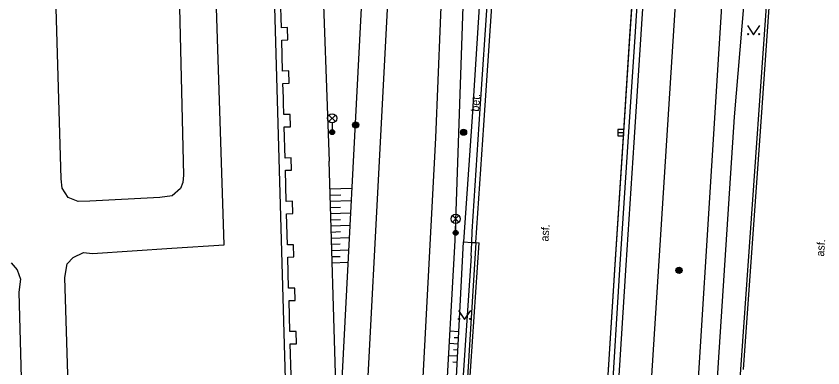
# Model space of a CAD drawing. Extents: x -599951 to -598963, y -1164095 to -1162939.
# Drawn here: x -599227.3 to -599161.8, y -1163894.3 to -1163865.7 of the extents above; entities that cross this region are included whole.
import ezdxf

# ---------------------------------------------------------------- set-up
doc = ezdxf.new("R2010")
doc.units = 0
for name, color, linetype in [('Level 1', 7, 'Continuous'), ('Level 10', 7, 'Continuous'), ('Level 11', 7, 'Continuous'), ('Level 13', 7, 'Continuous'), ('Level 14', 7, 'Continuous'), ('Level 15', 7, 'Continuous'), ('Level 25', 7, 'Continuous'), ('Level 27', 7, 'Continuous'), ('Level 33', 7, 'Continuous'), ('Level 36', 7, 'Continuous'), ('Level 40', 7, 'Continuous'), ('Level 54', 7, 'Continuous'), ('Level 9', 7, 'Continuous')]:
    doc.layers.add(name, color=color, linetype=linetype)

msp = doc.modelspace()

# ---------------------------------------------------------------- linework, layer by layer
at = {"layer": 'Level 1'}
msp.add_lwpolyline([(-599204.94, -1163894.86), (-599205.01, -1163892.33), (-599204.51, -1163892.32), (-599204.54, -1163891.32), (-599205.04, -1163891.33), (-599205.11, -1163888.8), (-599204.61, -1163888.79), (-599204.64, -1163887.79), (-599205.14, -1163887.8), (-599205.21, -1163885.27), (-599204.71, -1163885.26), (-599204.74, -1163884.26), (-599205.24, -1163884.27), (-599205.31, -1163881.74), (-599204.81, -1163881.73), (-599204.84, -1163880.73), (-599205.34, -1163880.74), (-599205.4, -1163878.21), (-599204.9, -1163878.2), (-599204.93, -1163877.2), (-599205.43, -1163877.22), (-599205.5, -1163874.69), (-599205, -1163874.67), (-599205.03, -1163873.67), (-599205.53, -1163873.69), (-599205.56, -1163872.71), (-599205.57, -1163872.31), (-599205.6, -1163871.16), (-599205.1, -1163871.14), (-599205.13, -1163870.14), (-599205.63, -1163870.16), (-599205.7, -1163867.63), (-599205.2, -1163867.61), (-599205.23, -1163866.61), (-599205.73, -1163866.63), (-599205.8, -1163864.1)], dxfattribs=at)
msp.add_lwpolyline([(-599204.94, -1163894.86), (-599205.01, -1163892.33), (-599204.51, -1163892.32), (-599204.54, -1163891.32), (-599205.04, -1163891.33), (-599205.11, -1163888.8), (-599204.61, -1163888.79), (-599204.64, -1163887.79), (-599205.14, -1163887.8), (-599205.21, -1163885.27), (-599204.71, -1163885.26), (-599204.74, -1163884.26), (-599205.24, -1163884.27), (-599205.31, -1163881.74), (-599204.81, -1163881.73), (-599204.84, -1163880.73), (-599205.34, -1163880.74), (-599205.4, -1163878.21), (-599204.9, -1163878.2), (-599204.93, -1163877.2), (-599205.43, -1163877.22), (-599205.5, -1163874.69), (-599205, -1163874.67), (-599205.03, -1163873.67), (-599205.53, -1163873.69), (-599205.56, -1163872.71), (-599205.57, -1163872.31), (-599205.6, -1163871.16), (-599205.1, -1163871.14), (-599205.13, -1163870.14), (-599205.63, -1163870.16), (-599205.7, -1163867.63), (-599205.2, -1163867.61), (-599205.23, -1163866.61), (-599205.73, -1163866.63), (-599205.8, -1163864.1)], dxfattribs=at)
at = {"layer": 'Level 10'}
for points in [[(-599162.85, -1163820.04), (-599165.66, -1163854.88), (-599168.46, -1163894.41), (-599171.02, -1163933.26), (-599173.23, -1163971.43)], [(-599162.85, -1163820.04), (-599165.66, -1163854.88), (-599168.46, -1163894.41), (-599171.02, -1163933.26), (-599173.23, -1163971.43)], [(-599189.93, -1163884.08), (-599190.81, -1163898.12), (-599192.15, -1163919.43), (-599193.42, -1163940)]]:
    msp.add_lwpolyline(points, dxfattribs=at)
at = {"layer": 'Level 11'}
for points in [[(-599189.93, -1163884.08), (-599189.3, -1163874.55), (-599188.64, -1163864.86), (-599187.94, -1163853.9), (-599187.18, -1163842.59), (-599186.48, -1163831.96), (-599185.77, -1163821.34), (-599185.17, -1163812.32)], [(-599189.93, -1163884.08), (-599189.3, -1163874.55), (-599188.64, -1163864.86), (-599187.94, -1163853.9), (-599187.18, -1163842.59), (-599186.48, -1163831.96), (-599185.77, -1163821.34), (-599185.17, -1163812.32)], [(-599172.9, -1163813.11), (-599173.38, -1163820.1), (-599174.07, -1163830.07), (-599174.74, -1163840.04), (-599175.4, -1163850), (-599175.95, -1163858.03), (-599176.47, -1163865.91), (-599177.1, -1163875.95), (-599177.75, -1163885.93), (-599178.52, -1163897.89), (-599179.3, -1163909.98), (-599179.92, -1163919.81), (-599180.51, -1163929.76), (-599181.12, -1163939.81), (-599181.72, -1163949.74), (-599182.32, -1163959.77), (-599182.91, -1163969.7), (-599183.49, -1163979.74), (-599184.17, -1163991.77), (-599185.17, -1164009.07), (-599185.26, -1164010.75)], [(-599172.9, -1163813.11), (-599173.38, -1163820.1), (-599174.07, -1163830.07), (-599174.74, -1163840.04), (-599175.4, -1163850), (-599175.95, -1163858.03), (-599176.47, -1163865.91), (-599177.1, -1163875.95), (-599177.75, -1163885.93), (-599178.52, -1163897.89), (-599179.3, -1163909.98), (-599179.92, -1163919.81), (-599180.51, -1163929.76), (-599181.12, -1163939.81), (-599181.72, -1163949.74), (-599182.32, -1163959.77), (-599182.91, -1163969.7), (-599183.49, -1163979.74), (-599184.17, -1163991.77), (-599185.17, -1164009.07), (-599185.26, -1164010.75)], [(-599197.62, -1163823.43), (-599198.25, -1163843.69), (-599199.2, -1163863.95), (-599200.91, -1163896.76), (-599202.16, -1163918.73), (-599203.28, -1163939.73), (-599203.53, -1163944.26), (-599203.97, -1163952.36)], [(-599197.62, -1163823.43), (-599198.25, -1163843.69), (-599199.2, -1163863.95), (-599200.91, -1163896.76), (-599202.16, -1163918.73), (-599203.28, -1163939.73), (-599203.53, -1163944.26), (-599203.97, -1163952.36)], [(-599203.73, -1163825.91), (-599201.86, -1163877.48)], [(-599180.56, -1163916.59), (-599180.15, -1163909.9), (-599179.38, -1163897.86), (-599178.63, -1163885.9), (-599177.98, -1163875.98), (-599177.45, -1163867.9), (-599176.79, -1163857.91), (-599176.26, -1163849.92), (-599175.61, -1163839.95), (-599175.02, -1163831.17)], [(-599165.76, -1163834.08), (-599167.29, -1163853.99), (-599168.96, -1163873.88)], [(-599165.44, -1163854.9), (-599166.83, -1163874.66), (-599168.22, -1163894.41)], [(-599189.35, -1163860.2), (-599189.55, -1163863.18), (-599190.25, -1163873.87), (-599190.93, -1163884.04)], [(-599191.62, -1163883.93), (-599190.97, -1163864.91)], [(-599168.96, -1163873.88), (-599170.26, -1163893.84), (-599171.48, -1163913.8)], [(-599195.85, -1163959.31), (-599194.73, -1163939.87), (-599193.59, -1163919.49), (-599192.41, -1163897.89), (-599191.62, -1163883.93)], [(-599190.93, -1163884.04), (-599190.27, -1163884.07)], [(-599190.27, -1163884.07), (-599189.93, -1163884.08)], [(-599190.62, -1163898.15), (-599189.67, -1163884.1)], [(-599189.93, -1163884.08), (-599189.67, -1163884.1)]]:
    msp.add_lwpolyline(points, dxfattribs=at)
at = {"layer": 'Level 13'}
for points in [[(-599178.43, -1164000.2), (-599167.24, -1163821.2)], [(-599191.12, -1163824.29), (-599193.21, -1163875.57)], [(-599196.66, -1163855.83), (-599199.93, -1163918.11)], [(-599173.6, -1163862.17), (-599182.35, -1163999.95)], [(-599193.21, -1163875.57), (-599199.31, -1163990.76)]]:
    msp.add_lwpolyline(points, dxfattribs=at)
at = {"layer": 'Level 14'}
msp.add_lwpolyline([(-599196.72, -1163973.49), (-599195.22, -1163960.9), (-599193.97, -1163939.87), (-599192.41, -1163912.27), (-599190.93, -1163884.04)], dxfattribs=at)
at = {"layer": 'Level 15'}
for points in [[(-599201.79, -1163879.73), (-599200.02, -1163879.67)], [(-599201.77, -1163880.23), (-599200.91, -1163880.2)], [(-599201.76, -1163880.73), (-599200.07, -1163880.68)], [(-599201.74, -1163881.23), (-599200.92, -1163881.2)], [(-599201.73, -1163881.73), (-599200.13, -1163881.68)], [(-599201.71, -1163882.23), (-599200.93, -1163882.2)], [(-599201.7, -1163882.73), (-599200.18, -1163882.68)], [(-599201.68, -1163883.23), (-599200.94, -1163883.2)], [(-599201.67, -1163883.73), (-599200.23, -1163883.68)], [(-599201.65, -1163884.23), (-599200.95, -1163884.2)], [(-599201.64, -1163884.73), (-599200.28, -1163884.69)], [(-599201.62, -1163885.23), (-599200.97, -1163885.21)], [(-599201.61, -1163885.73), (-599200.34, -1163885.69)], [(-599191.31, -1163891.34), (-599192.04, -1163891.3)], [(-599191.34, -1163891.84), (-599191.7, -1163891.82)], [(-599191.37, -1163892.34), (-599192.09, -1163892.3)], [(-599191.39, -1163892.83), (-599191.76, -1163892.82)], [(-599191.42, -1163893.33), (-599192.15, -1163893.3)], [(-599191.44, -1163893.83), (-599191.81, -1163893.81)]]:
    msp.add_lwpolyline(points, dxfattribs=at)
at = {"layer": 'Level 25'}
for centre, radius in [((-599199.7, -1163874.52), 0.25), ((-599199.7, -1163874.52), 0.2), ((-599199.7, -1163874.52), 0.15), ((-599199.7, -1163874.52), 0.1), ((-599199.7, -1163874.52), 0.05), ((-599190.94, -1163875.12), 0.25), ((-599190.94, -1163875.12), 0.2), ((-599190.94, -1163875.12), 0.15), ((-599190.94, -1163875.12), 0.1), ((-599190.94, -1163875.12), 0.05), ((-599173.44, -1163886.35), 0.25), ((-599173.44, -1163886.35), 0.2), ((-599173.44, -1163886.35), 0.15), ((-599173.44, -1163886.35), 0.1), ((-599173.44, -1163886.35), 0.05)]:
    msp.add_circle(centre, radius, dxfattribs=at)
at = {"layer": 'Level 27'}
msp.add_line((-599178.42, -1163875.15), (-599177.92, -1163875.15), dxfattribs=at)
msp.add_lwpolyline([(-599178.42, -1163875.4), (-599177.92, -1163875.4), (-599177.92, -1163874.9), (-599178.42, -1163874.9)], close=True, dxfattribs=at)
at = {"layer": 'Level 33'}
for p, q in [((-599201.875, -1163874.25), (-599201.345, -1163873.72)), ((-599201.875, -1163873.72), (-599201.345, -1163874.25)), ((-599201.61, -1163874.36), (-599201.61, -1163875.11)), ((-599191.845, -1163882.43), (-599191.315, -1163881.9)), ((-599191.845, -1163881.9), (-599191.315, -1163882.43)), ((-599191.58, -1163882.54), (-599191.58, -1163883.29))]:
    msp.add_line(p, q, dxfattribs=at)
for centre, radius in [((-599201.61, -1163873.985), 0.375), ((-599201.61, -1163875.11), 0.2), ((-599201.61, -1163875.11), 0.145), ((-599201.61, -1163875.11), 0.0876), ((-599191.58, -1163882.165), 0.375), ((-599191.58, -1163883.29), 0.2), ((-599191.58, -1163883.29), 0.145), ((-599191.58, -1163883.29), 0.0876)]:
    msp.add_circle(centre, radius, dxfattribs=at)
at = {"layer": 'Level 36'}
for points in [[(-599167.88, -1163866.45), (-599167.38, -1163867.2), (-599166.88, -1163866.45)], [(-599191.35, -1163889.6), (-599190.85, -1163890.35), (-599190.35, -1163889.6)]]:
    msp.add_lwpolyline(points, dxfattribs=at)
for centre in [(-599167.83, -1163867.15), (-599166.931, -1163867.15), (-599191.3, -1163890.3), (-599190.401, -1163890.3)]:
    msp.add_circle(centre, 0.05, dxfattribs=at)
at = {"layer": 'Level 54'}
for points in [[(-599207.39, -1163826.21), (-599205.38, -1163897.08)], [(-599210.37, -1163884.28), (-599211.95, -1163835.65)], [(-599223.61, -1163878.91), (-599224.73, -1163840.97)], [(-599214.56, -1163841.17), (-599213.67, -1163878.61)], [(-599213.67, -1163878.61), (-599213.74, -1163879.21)], [(-599223.54, -1163879.67), (-599223.61, -1163878.91)], [(-599213.74, -1163879.21), (-599213.93, -1163879.69)], [(-599223.04, -1163880.43), (-599223.54, -1163879.67)], [(-599213.93, -1163879.69), (-599214.59, -1163880.29)], [(-599222.23, -1163880.76), (-599223.04, -1163880.43)], [(-599221.29, -1163880.73), (-599222.23, -1163880.76)], [(-599215.61, -1163880.42), (-599221.29, -1163880.73)], [(-599214.59, -1163880.29), (-599215.61, -1163880.42)], [(-599221.06, -1163884.97), (-599214.64, -1163884.53)], [(-599214.64, -1163884.53), (-599210.37, -1163884.28)], [(-599223.13, -1163885.81), (-599222.63, -1163885.29)], [(-599222.63, -1163885.29), (-599221.79, -1163884.9)], [(-599221.79, -1163884.9), (-599221.06, -1163884.97)], [(-599227.66, -1163885.74), (-599227.19, -1163886.3)], [(-599223.32, -1163886.92), (-599223.13, -1163885.81)], [(-599227.19, -1163886.3), (-599226.91, -1163887.06)], [(-599226.91, -1163887.06), (-599227.06, -1163888.11)], [(-599221.59, -1163943.02), (-599223.32, -1163886.92)], [(-599227.06, -1163888.11), (-599225.54, -1163943.99)]]:
    msp.add_lwpolyline(points, dxfattribs=at)
at = {"layer": 'Level 9'}
for points in [[(-599190.27, -1163884.07), (-599190.23, -1163883.2), (-599189.59, -1163873.21), (-599188.97, -1163863.97), (-599188.32, -1163853.86), (-599187.56, -1163842.65), (-599186.85, -1163831.95), (-599186.13, -1163821.35), (-599185.57, -1163812.81)], [(-599190.27, -1163884.07), (-599190.23, -1163883.2), (-599189.59, -1163873.21), (-599188.97, -1163863.97), (-599188.32, -1163853.86), (-599187.56, -1163842.65), (-599186.85, -1163831.95), (-599186.13, -1163821.35), (-599185.57, -1163812.81)], [(-599173.33, -1163813.06), (-599173.85, -1163820.02), (-599174.57, -1163830.04), (-599175.22, -1163839.98), (-599175.88, -1163849.93), (-599176.42, -1163857.97), (-599177.03, -1163867.36), (-599177.61, -1163875.9), (-599178.24, -1163885.85), (-599178.98, -1163897.83), (-599179.77, -1163909.83), (-599180.41, -1163919.76), (-599181.02, -1163929.73), (-599181.63, -1163939.74), (-599182.23, -1163949.69), (-599182.82, -1163959.75), (-599183.42, -1163969.73), (-599184.01, -1163979.76), (-599184.69, -1163991.72), (-599185.65, -1164008.82), (-599186.25, -1164019.31), (-599186.77, -1164028.71), (-599187.18, -1164036.5)], [(-599173.33, -1163813.06), (-599173.85, -1163820.02), (-599174.57, -1163830.04), (-599175.22, -1163839.98), (-599175.88, -1163849.93), (-599176.42, -1163857.97), (-599177.03, -1163867.36), (-599177.61, -1163875.9), (-599178.24, -1163885.85), (-599178.98, -1163897.83), (-599179.77, -1163909.83), (-599180.41, -1163919.76), (-599181.02, -1163929.73), (-599181.63, -1163939.74), (-599182.23, -1163949.69), (-599182.82, -1163959.75), (-599183.42, -1163969.73), (-599184.01, -1163979.76), (-599184.69, -1163991.72), (-599185.65, -1164008.82), (-599186.25, -1164019.31), (-599186.77, -1164028.71), (-599187.18, -1164036.5)], [(-599175.08, -1163831.21), (-599175.67, -1163839.93), (-599176.33, -1163849.84), (-599176.82, -1163857.92), (-599177.45, -1163867.32), (-599178, -1163875.87), (-599178.65, -1163885.87), (-599179.42, -1163897.86), (-599180.19, -1163909.9), (-599180.61, -1163916.55)], [(-599206.5, -1163952.5), (-599203.95, -1163926.62), (-599203.22, -1163918.71), (-599201.28, -1163896.56), (-599201.86, -1163877.48)], [(-599206.5, -1163952.5), (-599203.95, -1163926.62), (-599203.22, -1163918.71), (-599201.28, -1163896.56), (-599201.86, -1163877.48)], [(-599190.33, -1163885.17), (-599190.27, -1163884.07)], [(-599190.33, -1163885.17), (-599191.19, -1163898.1)]]:
    msp.add_lwpolyline(points, dxfattribs=at)

# ---------------------------------------------------------------- texts
at = {"layer": 'Level 40'}
for s, p in [('bet.', (-599189.69, -1163873.46)), ('asf.', (-599184.05, -1163884.02)), ('asf.', (-599161.67, -1163885.24))]:
    msp.add_text(s, height=0.65, rotation=85.71, dxfattribs=at).set_placement(p)

doc.saveas('drawing.dxf')
